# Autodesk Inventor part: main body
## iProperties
Author: vincent molino
Shininess: 61.0
Angle Display Precision: 2
Document Length Units: 11272
Document Angle Units: 11286
Document Time Units: 11279
Document Mass Units: 11290
Document Length Units Precision: 3
Document Angle Units Precision: 2
Compacted: True
PropertySet Name: _Private Model Information
Created: 2002-01
Part Number: main body
Document SubType Name: Modeling
Designer: vincent molino
Control State: 0
Master: False
Checked Out: False
PropertySet Name: Design Tracking Control
Density: 0.0
Volumn: 0.0
Area: 0.0
PropertySet Name: Model Information
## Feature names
1. Extrusion1
2. Extrusion2
3. Extrusion3
4. Mirror1
5. Mirror2
6. Chamfer1
7. Fillet2
8. Fillet3
9. Extrusion4
